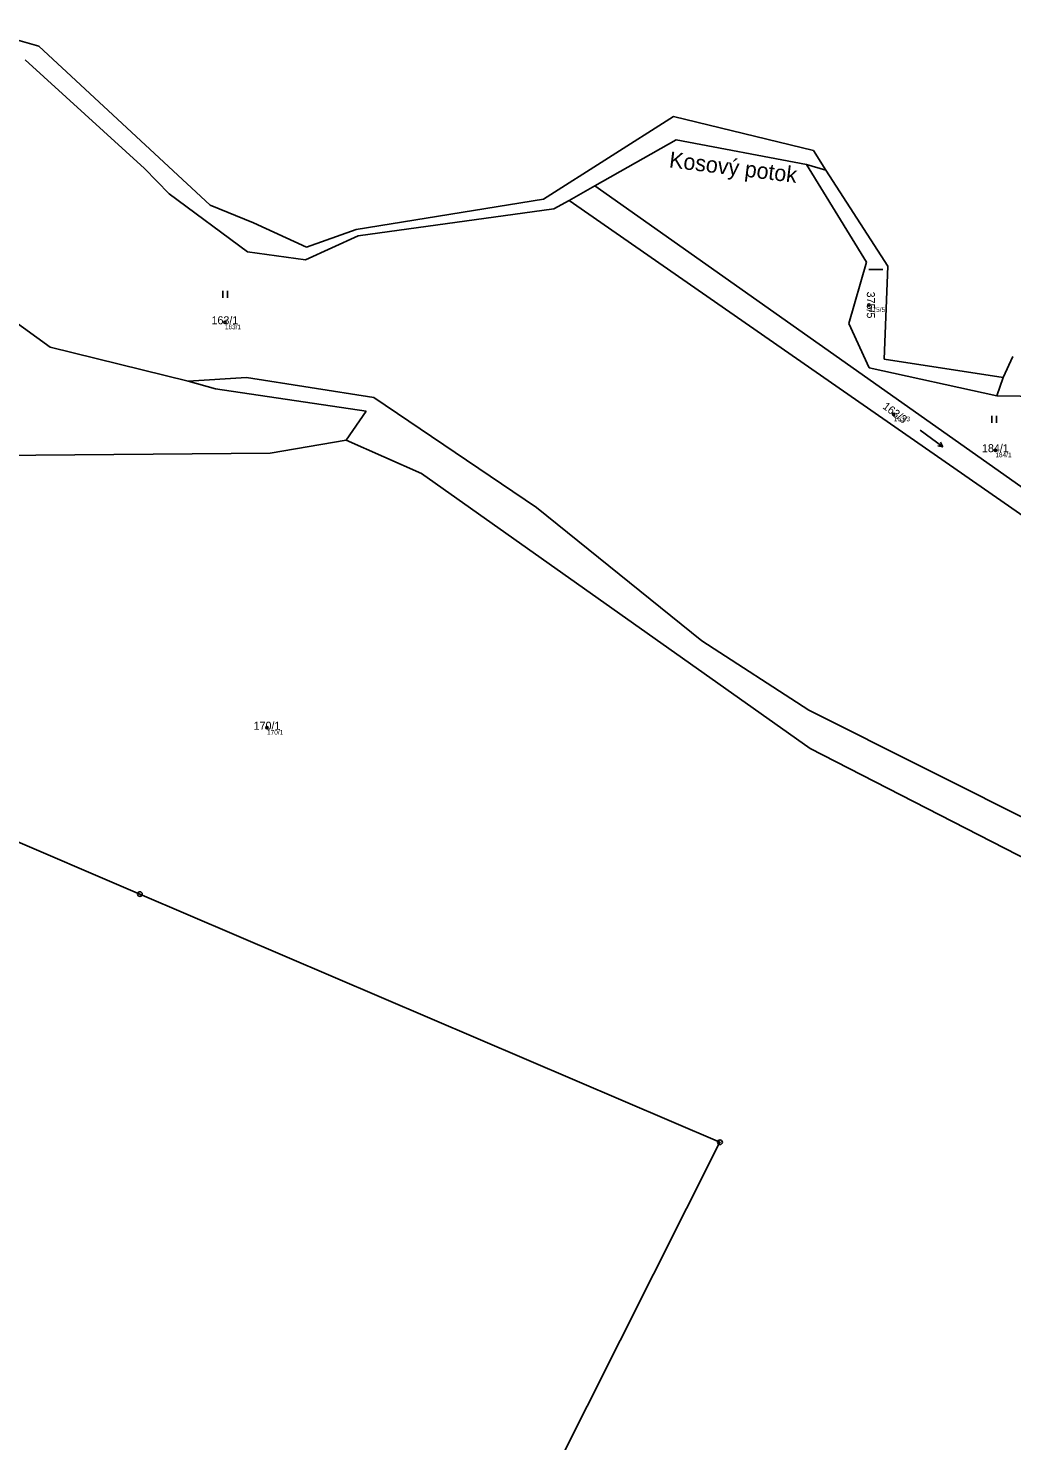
# Model space of a CAD drawing. Extents: x -867966 to -864255, y -1043242 to -1041327.
# Drawn here: x -865870.5 to -865661.4, y -1042193.8 to -1041893.7 of the extents above; entities that cross this region are included whole.
import ezdxf

# ---------------------------------------------------------------- set-up
doc = ezdxf.new("R2010")
doc.units = 0
for name, color, linetype in [('Definiční body', 7, 'Continuous'), ('Hranice parcel', 7, 'Continuous'), ('Parcelní čísla', 7, 'Continuous'), ('Pop  PČ popisy', 7, 'Continuous'), ('Značky bodu BP', 7, 'Continuous'), ('Značky kultur', 7, 'Continuous')]:
    doc.layers.add(name, color=color, linetype=linetype)

msp = doc.modelspace()

# ---------------------------------------------------------------- linework, layer by layer
at = {"layer": 'Definiční body'}
for centre in [(-865691.76, -1041952.46), (-865828.65, -1041956.13), (-865686.46, -1041975.68), (-865664.88, -1041983.32), (-865819.7, -1042042.28)]:
    msp.add_circle(centre, 0.25, dxfattribs=at)
at = {"layer": 'Hranice parcel'}
for p, q in [((-865868.21, -1041897.47), (-865881.48, -1041893.66)), ((-865831.78, -1041931.23), (-865868.21, -1041897.47)), ((-865871.13, -1041900.37), (-865845.75, -1041923.48)), ((-865733.27, -1041912.4), (-865760.93, -1041930)), ((-865703.56, -1041919.67), (-865733.27, -1041912.4)), ((-865750.01, -1041927.15), (-865732.73, -1041917.39)), ((-865732.73, -1041917.39), (-865704.99, -1041922.59)), ((-865703.56, -1041919.67), (-865700.9, -1041923.8)), ((-865845.75, -1041923.48), (-865840.46, -1041928.83)), ((-865704.99, -1041922.59), (-865700.9, -1041923.8)), ((-865704.99, -1041922.59), (-865692.3, -1041943.35)), ((-865700.9, -1041923.8), (-865700.12, -1041925.01)), ((-865750.01, -1041927.15), (-865755.49, -1041930.24)), ((-865750.01, -1041927.15), (-865632, -1042010.47)), ((-865687.75, -1041944.2), (-865700.12, -1041925.01)), ((-865840.46, -1041928.83), (-865823.86, -1041941.14)), ((-865760.93, -1041930), (-865800.71, -1041936.44)), ((-865758.71, -1041932.06), (-865755.49, -1041930.24)), ((-865629.59, -1042017.79), (-865755.49, -1041930.24)), ((-865822.56, -1041935.01), (-865831.78, -1041931.23)), ((-865800.34, -1041937.76), (-865758.71, -1041932.06)), ((-865811.33, -1041940.21), (-865822.56, -1041935.01)), ((-865800.71, -1041936.44), (-865811.33, -1041940.21)), ((-865811.49, -1041942.89), (-865800.34, -1041937.76)), ((-865823.86, -1041941.14), (-865811.49, -1041942.89)), ((-865692.3, -1041943.35), (-865696, -1041956.41)), ((-865688.5, -1041963.99), (-865687.75, -1041944.2)), ((-865865.78, -1041961.42), (-865881.06, -1041950.39)), ((-865696, -1041956.41), (-865691.67, -1041965.82)), ((-865836.42, -1041968.65), (-865865.78, -1041961.42)), ((-865661.18, -1041963.4), (-865663.19, -1041967.85)), ((-865691.67, -1041965.82), (-865664.54, -1041971.79)), ((-865663.19, -1041967.85), (-865688.5, -1041963.99)), ((-865836.42, -1041968.65), (-865824.04, -1041967.9)), ((-865830.63, -1041970.25), (-865836.42, -1041968.65)), ((-865824.04, -1041967.9), (-865797, -1041972.13)), ((-865664.54, -1041971.79), (-865663.19, -1041967.85)), ((-865798.64, -1041975.01), (-865830.63, -1041970.25)), ((-865797, -1041972.13), (-865762.41, -1041995.47)), ((-865664.54, -1041971.79), (-865650, -1041971.96)), ((-865802.9, -1041981.17), (-865798.64, -1041975.01)), ((-865819.05, -1041983.94), (-865802.9, -1041981.17)), ((-865786.85, -1041988.28), (-865802.9, -1041981.17)), ((-865948.59, -1041985.08), (-865819.05, -1041983.94)), ((-865704.23, -1042046.72), (-865786.85, -1041988.28)), ((-865762.41, -1041995.47), (-865727.24, -1042023.8)), ((-865970.97, -1042024.51), (-865846.71, -1042077.65)), ((-865727.24, -1042023.8), (-865704.5, -1042038.59)), ((-865704.5, -1042038.59), (-865636.25, -1042072.8)), ((-865638.61, -1042080.38), (-865704.23, -1042046.72)), ((-865846.71, -1042077.65), (-865723.41, -1042130.38)), ((-865723.41, -1042130.38), (-865809.99, -1042302.33))]:
    msp.add_line(p, q, dxfattribs=at)
at = {"layer": 'Značky bodu BP'}
for centre, radius in [((-865846.71, -1042077.65), 0.5), ((-865846.71, -1042077.65), 0.0303), ((-865723.41, -1042130.38), 0.5), ((-865723.41, -1042130.38), 0.0303)]:
    msp.add_circle(centre, radius, dxfattribs=at)
at = {"layer": 'Značky kultur'}
for p, q in [((-865691.79, -1041944.92), (-865688.79, -1041944.92)), ((-865829.09, -1041950.95), (-865829.09, -1041949.45)), ((-865828.09, -1041950.95), (-865828.09, -1041949.45)), ((-865665.66, -1041977.52), (-865665.66, -1041976.02)), ((-865664.66, -1041977.52), (-865664.66, -1041976.02)), ((-865680.87, -1041979.05), (-865676.01, -1041982.58)), ((-865676.01, -1041982.58), (-865676.51, -1041981.6)), ((-865676.01, -1041982.58), (-865677.1, -1041982.41))]:
    msp.add_line(p, q, dxfattribs=at)

# ---------------------------------------------------------------- texts
at = {"layer": 'Definiční body'}
for s, p in [('375/5', (-865691.76, -1041953.95)), ('163/1', (-865828.65, -1041957.62)), ('163/3', (-865686.46, -1041977.17)), ('184/1', (-865664.88, -1041984.81)), ('170/1', (-865819.7, -1042043.77))]:
    msp.add_text(s, height=1, dxfattribs=at).set_placement(p)
at = {"layer": 'Parcelní čísla'}
for s, rotation, p in [('375/5', 270, (-865692.19, -1041949.62)), ('163/3', 323, (-865688.98, -1041974.31))]:
    msp.add_text(s, height=1.7, rotation=rotation, dxfattribs=at).set_placement(p)
for s, p in [('163/1', (-865831.49, -1041956.56)), ('184/1', (-865667.72, -1041983.74)), ('170/1', (-865822.54, -1042042.71))]:
    msp.add_text(s, height=1.7, dxfattribs=at).set_placement(p)
at = {"layer": 'Pop  PČ popisy'}
msp.add_text('Kosový potok', height=3.4, rotation=353, dxfattribs=at).set_placement((-865734.34, -1041923.21))

doc.saveas('drawing.dxf')
